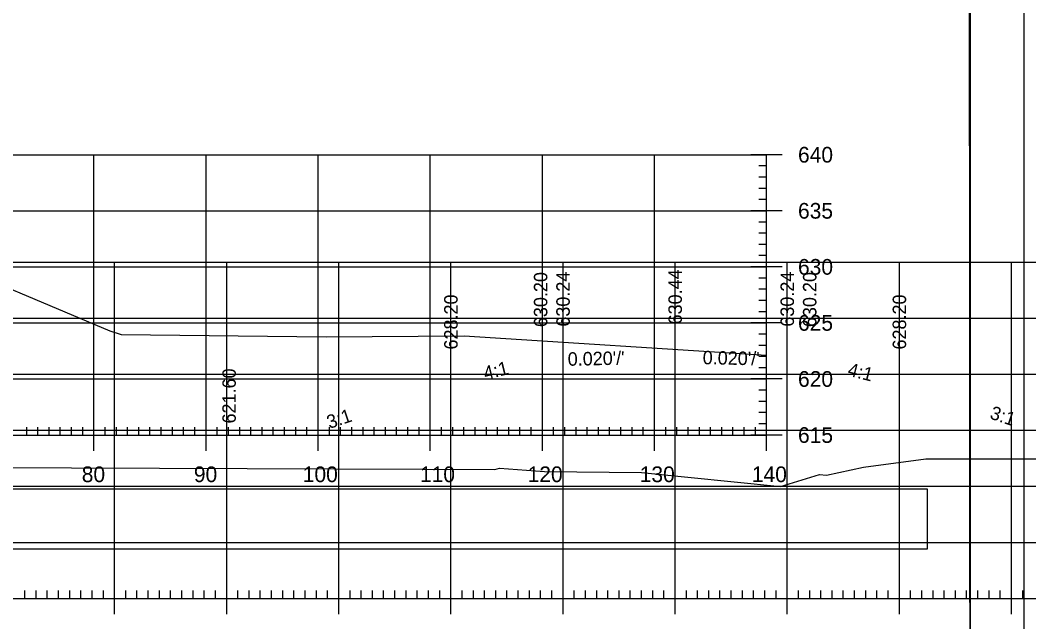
# Model space of a CAD drawing. Extents: x 1381471 to 1382703, y 370300 to 371487.
# Drawn here: x 1382078.2 to 1382168.2, y 370865 to 370918.7 of the extents above; entities that cross this region are included whole.
import ezdxf

# ---------------------------------------------------------------- set-up
doc = ezdxf.new("R2010")
doc.units = 0
for name, color, linetype in [('Level 18', 7, 'Continuous'), ('Level 22', 7, 'Continuous'), ('Level 26', 7, 'Continuous'), ('Level 4', 7, 'Continuous'), ('Level 45', 7, 'Continuous'), ('Level 5', 7, 'Continuous'), ('Level 6', 7, 'Continuous')]:
    doc.layers.add(name, color=color, linetype=linetype)

msp = doc.modelspace()

# ---------------------------------------------------------------- linework, layer by layer
at = {"layer": 'Level 18'}
msp.add_lwpolyline([(1381976.279, 370900.362), (1381991.073, 370900.364), (1381992.94, 370900.422), (1381995.782, 370900.467), (1381996.061, 370900.488), (1382000.059, 370900.431), (1382006.558, 370900.36), (1382013.108, 370900.141), (1382016.775, 370900.043), (1382017.51, 370899.977), (1382020.418, 370899.764), (1382029.864, 370899.719), (1382031.303, 370899.706), (1382033.456, 370899.737), (1382044.888, 370899.74), (1382048.398, 370899.766), (1382051.825, 370899.483), (1382064.294, 370898.771), (1382069.542, 370897.991), (1382086.188, 370890.986), (1382087.194, 370890.67), (1382105.489, 370890.444), (1382117.783, 370890.544), (1382144.772, 370888.804)], dxfattribs=at)
at = {"layer": 'Level 22'}
for p, q in [((1381864.772, 370906.691), (1382144.772, 370906.691)), ((1382084.772, 370881.691), (1382084.772, 370906.691)), ((1382094.772, 370881.691), (1382094.772, 370906.691)), ((1382104.772, 370881.691), (1382104.772, 370906.691)), ((1382114.772, 370881.691), (1382114.772, 370906.691)), ((1382124.772, 370881.691), (1382124.772, 370906.691)), ((1382134.772, 370881.691), (1382134.772, 370906.691)), ((1382144.772, 370881.691), (1382144.772, 370906.691)), ((1381864.772, 370901.691), (1382144.772, 370901.691)), ((1381864.772, 370896.691), (1382144.772, 370896.691)), ((1381864.772, 370891.691), (1382144.772, 370891.691)), ((1381864.772, 370886.691), (1382144.772, 370886.691)), ((1381864.772, 370881.691), (1382144.772, 370881.691))]:
    msp.add_line(p, q, dxfattribs=at)
at = {"layer": 'Level 26'}
for points in [[(1381834.365, 370974.304), (1382167.705, 370974.304), (1382167.705, 370760.966), (1381834.365, 370760.966)], [(1382080.692, 370970.409), (1382100.312, 370970.409), (1382100.312, 370960.529), (1382116.424, 370960.529), (1382139.624, 370960.529), (1382139.624, 370927.859), (1382162.831, 370927.859), (1382162.952, 370764.949), (1381846.772, 370764.949), (1381846.772, 370970.409)]]:
    msp.add_lwpolyline(points, close=True, dxfattribs=at)
at = {"layer": 'Level 4'}
for p, q in [((1382146.172, 370906.691), (1382143.372, 370906.691)), ((1382144.772, 370881.691), (1382144.772, 370906.691)), ((1382144.772, 370905.691), (1382144.072, 370905.691)), ((1382144.772, 370904.691), (1382144.072, 370904.691)), ((1382144.772, 370903.691), (1382144.072, 370903.691)), ((1382144.772, 370902.691), (1382144.072, 370902.691)), ((1382146.172, 370901.691), (1382143.372, 370901.691)), ((1382144.772, 370900.691), (1382144.072, 370900.691)), ((1382144.772, 370899.691), (1382144.072, 370899.691)), ((1382144.772, 370898.691), (1382144.072, 370898.691)), ((1382144.772, 370897.691), (1382144.072, 370897.691)), ((1382146.172, 370896.691), (1382143.372, 370896.691)), ((1382144.772, 370895.691), (1382144.072, 370895.691)), ((1382144.772, 370894.691), (1382144.072, 370894.691)), ((1382144.772, 370893.691), (1382144.072, 370893.691)), ((1382144.772, 370892.691), (1382144.072, 370892.691)), ((1382146.172, 370891.691), (1382143.372, 370891.691)), ((1382144.772, 370890.691), (1382144.072, 370890.691)), ((1382144.772, 370889.691), (1382144.072, 370889.691)), ((1382144.772, 370888.691), (1382144.072, 370888.691)), ((1382144.772, 370887.691), (1382144.072, 370887.691)), ((1382146.172, 370886.691), (1382143.372, 370886.691)), ((1382144.772, 370885.691), (1382144.072, 370885.691)), ((1382144.772, 370884.691), (1382144.072, 370884.691)), ((1382144.772, 370883.691), (1382144.072, 370883.691)), ((1382078.772, 370881.691), (1382078.772, 370882.391)), ((1382079.772, 370881.691), (1382079.772, 370882.391)), ((1382080.772, 370881.691), (1382080.772, 370882.391)), ((1382081.772, 370881.691), (1382081.772, 370882.391)), ((1382082.772, 370881.691), (1382082.772, 370882.391)), ((1382083.772, 370881.691), (1382083.772, 370882.391)), ((1382084.772, 370880.291), (1382084.772, 370883.091)), ((1382085.772, 370881.691), (1382085.772, 370882.391)), ((1382086.772, 370881.691), (1382086.772, 370882.391)), ((1382087.772, 370881.691), (1382087.772, 370882.391)), ((1382088.772, 370881.691), (1382088.772, 370882.391)), ((1382089.772, 370881.691), (1382089.772, 370882.391)), ((1382090.772, 370881.691), (1382090.772, 370882.391)), ((1382091.772, 370881.691), (1382091.772, 370882.391)), ((1382092.772, 370881.691), (1382092.772, 370882.391)), ((1382093.772, 370881.691), (1382093.772, 370882.391)), ((1382094.772, 370880.291), (1382094.772, 370883.091)), ((1382095.772, 370881.691), (1382095.772, 370882.391)), ((1382096.772, 370881.691), (1382096.772, 370882.391)), ((1382097.772, 370881.691), (1382097.772, 370882.391)), ((1382098.772, 370881.691), (1382098.772, 370882.391)), ((1382099.772, 370881.691), (1382099.772, 370882.391)), ((1382100.772, 370881.691), (1382100.772, 370882.391)), ((1382101.772, 370881.691), (1382101.772, 370882.391)), ((1382102.772, 370881.691), (1382102.772, 370882.391)), ((1382103.772, 370881.691), (1382103.772, 370882.391)), ((1382104.772, 370880.291), (1382104.772, 370883.091)), ((1382105.772, 370881.691), (1382105.772, 370882.391)), ((1382106.772, 370881.691), (1382106.772, 370882.391)), ((1382107.772, 370881.691), (1382107.772, 370882.391)), ((1382108.772, 370881.691), (1382108.772, 370882.391)), ((1382109.772, 370881.691), (1382109.772, 370882.391)), ((1382110.772, 370881.691), (1382110.772, 370882.391)), ((1382111.772, 370881.691), (1382111.772, 370882.391)), ((1382112.772, 370881.691), (1382112.772, 370882.391)), ((1382113.772, 370881.691), (1382113.772, 370882.391)), ((1382114.772, 370880.291), (1382114.772, 370883.091)), ((1382115.772, 370881.691), (1382115.772, 370882.391)), ((1382116.772, 370881.691), (1382116.772, 370882.391)), ((1382117.772, 370881.691), (1382117.772, 370882.391)), ((1382118.772, 370881.691), (1382118.772, 370882.391)), ((1382119.772, 370881.691), (1382119.772, 370882.391)), ((1382120.772, 370881.691), (1382120.772, 370882.391)), ((1382121.772, 370881.691), (1382121.772, 370882.391)), ((1382122.772, 370881.691), (1382122.772, 370882.391)), ((1382123.772, 370881.691), (1382123.772, 370882.391)), ((1382124.772, 370880.291), (1382124.772, 370883.091)), ((1382125.772, 370881.691), (1382125.772, 370882.391)), ((1382126.772, 370881.691), (1382126.772, 370882.391)), ((1382127.772, 370881.691), (1382127.772, 370882.391)), ((1382128.772, 370881.691), (1382128.772, 370882.391)), ((1382129.772, 370881.691), (1382129.772, 370882.391)), ((1382130.772, 370881.691), (1382130.772, 370882.391)), ((1382131.772, 370881.691), (1382131.772, 370882.391)), ((1382132.772, 370881.691), (1382132.772, 370882.391)), ((1382133.772, 370881.691), (1382133.772, 370882.391)), ((1382134.772, 370880.291), (1382134.772, 370883.091)), ((1382135.772, 370881.691), (1382135.772, 370882.391)), ((1382136.772, 370881.691), (1382136.772, 370882.391)), ((1382137.772, 370881.691), (1382137.772, 370882.391)), ((1382138.772, 370881.691), (1382138.772, 370882.391)), ((1382139.772, 370881.691), (1382139.772, 370882.391)), ((1382140.772, 370881.691), (1382140.772, 370882.391)), ((1382141.772, 370881.691), (1382141.772, 370882.391)), ((1382142.772, 370881.691), (1382142.772, 370882.391)), ((1382143.772, 370881.691), (1382143.772, 370882.391)), ((1382144.772, 370882.691), (1382144.072, 370882.691)), ((1382144.772, 370880.291), (1382144.772, 370883.091)), ((1381864.772, 370881.691), (1382144.772, 370881.691)), ((1382146.172, 370881.691), (1382143.372, 370881.691))]:
    msp.add_line(p, q, dxfattribs=at)
at = {"layer": 'Level 45'}
for p, q in [((1381996.613, 370897.12), (1382276.613, 370897.12)), ((1382086.613, 370867.12), (1382086.613, 370897.12)), ((1382096.613, 370867.12), (1382096.613, 370897.12)), ((1382106.613, 370867.12), (1382106.613, 370897.12)), ((1382116.613, 370867.12), (1382116.613, 370897.12)), ((1382126.613, 370867.12), (1382126.613, 370897.12)), ((1382136.613, 370867.12), (1382136.613, 370897.12)), ((1382146.613, 370867.12), (1382146.613, 370897.12)), ((1382156.613, 370867.12), (1382156.613, 370897.12)), ((1382166.613, 370867.12), (1382166.613, 370897.12)), ((1381996.613, 370892.12), (1382276.613, 370892.12)), ((1381996.613, 370887.12), (1382276.613, 370887.12)), ((1381996.613, 370882.12), (1382276.613, 370882.12)), ((1381996.613, 370877.12), (1382276.613, 370877.12)), ((1381996.613, 370872.12), (1382276.613, 370872.12)), ((1382086.613, 370865.72), (1382086.613, 370868.52)), ((1382096.613, 370865.72), (1382096.613, 370868.52)), ((1382106.613, 370865.72), (1382106.613, 370868.52)), ((1382116.613, 370865.72), (1382116.613, 370868.52)), ((1382126.613, 370865.72), (1382126.613, 370868.52)), ((1382136.613, 370865.72), (1382136.613, 370868.52)), ((1382146.613, 370865.72), (1382146.613, 370868.52)), ((1382156.613, 370865.72), (1382156.613, 370868.52)), ((1382166.613, 370865.72), (1382166.613, 370868.52)), ((1381996.613, 370867.12), (1382276.613, 370867.12)), ((1381996.613, 370867.12), (1382276.613, 370867.12)), ((1382078.613, 370867.12), (1382078.613, 370867.82)), ((1382079.613, 370867.12), (1382079.613, 370867.82)), ((1382080.613, 370867.12), (1382080.613, 370867.82)), ((1382081.613, 370867.12), (1382081.613, 370867.82)), ((1382082.613, 370867.12), (1382082.613, 370867.82)), ((1382083.613, 370867.12), (1382083.613, 370867.82)), ((1382084.613, 370867.12), (1382084.613, 370867.82)), ((1382085.613, 370867.12), (1382085.613, 370867.82)), ((1382087.613, 370867.12), (1382087.613, 370867.82)), ((1382088.613, 370867.12), (1382088.613, 370867.82)), ((1382089.613, 370867.12), (1382089.613, 370867.82)), ((1382090.613, 370867.12), (1382090.613, 370867.82)), ((1382091.613, 370867.12), (1382091.613, 370867.82)), ((1382092.613, 370867.12), (1382092.613, 370867.82)), ((1382093.613, 370867.12), (1382093.613, 370867.82)), ((1382094.613, 370867.12), (1382094.613, 370867.82)), ((1382095.613, 370867.12), (1382095.613, 370867.82)), ((1382097.613, 370867.12), (1382097.613, 370867.82)), ((1382098.613, 370867.12), (1382098.613, 370867.82)), ((1382099.613, 370867.12), (1382099.613, 370867.82)), ((1382100.613, 370867.12), (1382100.613, 370867.82)), ((1382101.613, 370867.12), (1382101.613, 370867.82)), ((1382102.613, 370867.12), (1382102.613, 370867.82)), ((1382103.613, 370867.12), (1382103.613, 370867.82)), ((1382104.613, 370867.12), (1382104.613, 370867.82)), ((1382105.613, 370867.12), (1382105.613, 370867.82)), ((1382107.613, 370867.12), (1382107.613, 370867.82)), ((1382108.613, 370867.12), (1382108.613, 370867.82)), ((1382109.613, 370867.12), (1382109.613, 370867.82)), ((1382110.613, 370867.12), (1382110.613, 370867.82)), ((1382111.613, 370867.12), (1382111.613, 370867.82)), ((1382112.613, 370867.12), (1382112.613, 370867.82)), ((1382113.613, 370867.12), (1382113.613, 370867.82)), ((1382114.613, 370867.12), (1382114.613, 370867.82)), ((1382115.613, 370867.12), (1382115.613, 370867.82)), ((1382117.613, 370867.12), (1382117.613, 370867.82)), ((1382118.613, 370867.12), (1382118.613, 370867.82)), ((1382119.613, 370867.12), (1382119.613, 370867.82)), ((1382120.613, 370867.12), (1382120.613, 370867.82)), ((1382121.613, 370867.12), (1382121.613, 370867.82)), ((1382122.613, 370867.12), (1382122.613, 370867.82)), ((1382123.613, 370867.12), (1382123.613, 370867.82)), ((1382124.613, 370867.12), (1382124.613, 370867.82)), ((1382125.613, 370867.12), (1382125.613, 370867.82)), ((1382127.613, 370867.12), (1382127.613, 370867.82)), ((1382128.613, 370867.12), (1382128.613, 370867.82)), ((1382129.613, 370867.12), (1382129.613, 370867.82)), ((1382130.613, 370867.12), (1382130.613, 370867.82)), ((1382131.613, 370867.12), (1382131.613, 370867.82)), ((1382132.613, 370867.12), (1382132.613, 370867.82)), ((1382133.613, 370867.12), (1382133.613, 370867.82)), ((1382134.613, 370867.12), (1382134.613, 370867.82)), ((1382135.613, 370867.12), (1382135.613, 370867.82)), ((1382137.613, 370867.12), (1382137.613, 370867.82)), ((1382138.613, 370867.12), (1382138.613, 370867.82)), ((1382139.613, 370867.12), (1382139.613, 370867.82)), ((1382140.613, 370867.12), (1382140.613, 370867.82)), ((1382141.613, 370867.12), (1382141.613, 370867.82)), ((1382142.613, 370867.12), (1382142.613, 370867.82)), ((1382143.613, 370867.12), (1382143.613, 370867.82)), ((1382144.613, 370867.12), (1382144.613, 370867.82)), ((1382145.613, 370867.12), (1382145.613, 370867.82)), ((1382147.613, 370867.12), (1382147.613, 370867.82)), ((1382148.613, 370867.12), (1382148.613, 370867.82)), ((1382149.613, 370867.12), (1382149.613, 370867.82)), ((1382150.613, 370867.12), (1382150.613, 370867.82)), ((1382151.613, 370867.12), (1382151.613, 370867.82)), ((1382152.613, 370867.12), (1382152.613, 370867.82)), ((1382153.613, 370867.12), (1382153.613, 370867.82)), ((1382154.613, 370867.12), (1382154.613, 370867.82)), ((1382155.613, 370867.12), (1382155.613, 370867.82)), ((1382157.613, 370867.12), (1382157.613, 370867.82)), ((1382158.613, 370867.12), (1382158.613, 370867.82)), ((1382159.613, 370867.12), (1382159.613, 370867.82)), ((1382160.613, 370867.12), (1382160.613, 370867.82)), ((1382161.613, 370867.12), (1382161.613, 370867.82)), ((1382162.613, 370867.12), (1382162.613, 370867.82)), ((1382163.613, 370867.12), (1382163.613, 370867.82)), ((1382164.613, 370867.12), (1382164.613, 370867.82)), ((1382165.613, 370867.12), (1382165.613, 370867.82)), ((1382167.613, 370867.12), (1382167.613, 370867.82))]:
    msp.add_line(p, q, dxfattribs=at)
msp.add_lwpolyline([(1381996.613, 370881.285), (1382011.746, 370881.192), (1382013.463, 370881.176), (1382017.774, 370880.957), (1382059.233, 370878.871), (1382074.892, 370878.808), (1382114.146, 370878.654), (1382120.535, 370878.629), (1382120.937, 370878.724), (1382124.974, 370878.432), (1382133.617, 370878.352), (1382146.02, 370877.097), (1382149.495, 370878.17), (1382150.118, 370878.114), (1382153.412, 370878.814), (1382158.962, 370879.579), (1382184.218, 370879.561)], dxfattribs=at)
at = {"layer": 'Level 6'}
msp.add_line((1382162.952, 370764.949), (1382162.952, 370970.409), dxfattribs=at)
msp.add_lwpolyline([(1381850.409, 370871.532), (1382159.135, 370871.532), (1382159.135, 370876.854), (1381850.409, 370876.854)], close=True, dxfattribs=at)

# ---------------------------------------------------------------- texts
at = {"layer": 'Level 45'}
for s, rotation, p in [('630.20', 90, (1382125.213, 370891.317)), ('630.24', 90, (1382127.213, 370891.357)), ('630.44', 90, (1382137.213, 370891.557)), ('630.24', 90, (1382147.213, 370891.357)), ('630.20', 90, (1382149.213, 370891.317)), ('628.20', 90, (1382117.213, 370889.317)), ('628.20', 90, (1382157.213, 370889.317)), ("0.020'/'", 1.14576, (1382127.042, 370887.866)), ("0.020'/'", 358.85424, (1382139.062, 370888.008)), ('4:1', 14.03624, (1382119.685, 370886.601)), ('4:1', 345.96376, (1382151.928, 370887.004)), ('621.60', 90, (1382097.427, 370882.722)), ('3:1', 341.56507, (1382164.606, 370883.18)), ('3:1', 18.43493, (1382105.773, 370882.231))]:
    msp.add_text(s, height=1.2, rotation=rotation, dxfattribs=at).set_placement(p)
at = {"layer": 'Level 5'}
for s, p in [('640', (1382147.572, 370905.991)), ('635', (1382147.572, 370900.991)), ('630', (1382147.572, 370895.991)), ('625', (1382147.572, 370890.991)), ('620', (1382147.572, 370885.991)), ('615', (1382147.572, 370880.991)), ('80', (1382083.686, 370877.491)), ('90', (1382093.686, 370877.491)), ('100', (1382103.4, 370877.491)), ('110', (1382113.852, 370877.491)), ('120', (1382123.455, 370877.491)), ('130', (1382133.455, 370877.491)), ('140', (1382143.455, 370877.491))]:
    msp.add_text(s, height=1.4, dxfattribs=at).set_placement(p)

doc.saveas('drawing.dxf')
